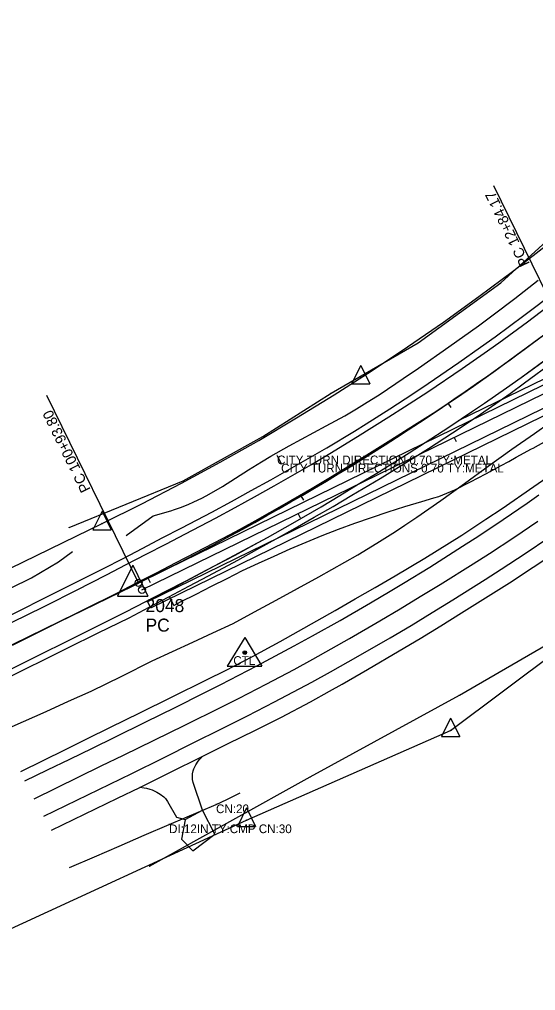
# Model space of a CAD drawing. Extents: x 1674300 to 1677920, y 225056 to 231852.
# Drawn here: x 1676496 to 1676793, y 227452 to 228011 of the extents above; entities that cross this region are included whole.
import ezdxf

# ---------------------------------------------------------------- set-up
doc = ezdxf.new("R2010")
doc.units = 0
for name, color, linetype in [('R_Horz Alg', 7, 'Continuous'), ('R_Horz Alg Annot', 7, 'Continuous'), ('R_Proposed Const Limits_Fill', 7, 'Continuous'), ('R_Proposed Road_Lane', 7, 'Continuous'), ('R_Proposed Road_Shoulder', 7, 'Continuous'), ('S_CAL_CORNER', 7, 'Continuous'), ('S_CAL_CORNER_ANNOT', 7, 'Continuous'), ('S_DITCHLINE', 7, 'Continuous'), ('S_DRG_PT_SYM', 7, 'Continuous'), ('S_EDGE_BITUMINOUS', 7, 'Continuous'), ('S_EDGE_PAVEMENT', 7, 'Continuous'), ('S_EXIST_ROW', 7, 'Continuous'), ('S_EXISTING_ALIGNMENT', 7, 'Continuous'), ('S_FIBER_OPTIC_CABLE', 7, 'Continuous'), ('S_GRAVEL_ROAD', 7, 'Continuous'), ('S_MSC_PT_SYM', 7, 'Continuous'), ('S_PAVEMENT_CROWN', 7, 'Continuous'), ('S_PRIMARY_CTL', 7, 'Continuous'), ('S_SHOULDER', 7, 'Continuous'), ('S_SIDE_DRAIN', 7, 'Continuous'), ('S_SIDE_DRAIN_ANNOT', 7, 'Continuous'), ('S_SIGN', 7, 'Continuous'), ('S_SIGN_ANNOT', 7, 'Continuous'), ('S_UTL_PT_SYM', 7, 'Continuous')]:
    doc.layers.add(name, color=color, linetype=linetype)

msp = doc.modelspace()

# ---------------------------------------------------------------- linework, layer by layer
at = {"layer": 'R_Horz Alg'}
for p, q in [((1676566.75, 227682.84), (1676822.03, 227807.69)), ((1676115.61, 227467.2), (1676564.78, 227686.88))]:
    msp.add_line(p, q, dxfattribs=at)
msp.add_arc((1675928.16, 228988.54), 1449, 296.0624, 0.80558, dxfattribs=at)
at = {"layer": 'R_Horz Alg Annot'}
msp.add_line((1676564.78, 227686.88), (1677389.93, 228090.45), dxfattribs=at)
for points in [[(1676822.03, 227807.69), (1676769.3, 227915.48)], [(1676564.78, 227686.88), (1676512.05, 227794.68)], [(1676744.64, 227787.84), (1676742.95, 227790.32)], [(1676747.73, 227768.01), (1676746.42, 227770.71)], [(1676659.89, 227734.4), (1676658.38, 227736.99)], [(1676657.9, 227724.08), (1676656.58, 227726.77)], [(1676571.67, 227686.93), (1676570.34, 227689.61)]]:
    msp.add_lwpolyline(points, dxfattribs=at)
for centre in [(1676564.78, 227686.88), (1676566.75, 227682.84)]:
    msp.add_circle(centre, 2, dxfattribs=at)
at = {"layer": 'R_Proposed Const Limits_Fill'}
msp.add_line((1676585.15, 227673.94), (1676582.55, 227679.05), dxfattribs=at)
msp.add_lwpolyline([(1676585.15, 227673.94), (1676588.94, 227675.93), (1676597.88, 227680.41), (1676606.76, 227685.02), (1676615.73, 227689.44), (1676624.67, 227693.92), (1676633.73, 227698.17), (1676642.85, 227702.29), (1676651.99, 227706.38), (1676661.2, 227710.33), (1676670.5, 227714.1), (1676679.82, 227717.84), (1676689.32, 227721.21), (1676698.84, 227724.53), (1676708.42, 227727.76), (1676718.1, 227730.78), (1676727.79, 227733.78), (1676734.61, 227735.81), (1676737.54, 227736.67), (1676746.79, 227740.54), (1676755.71, 227745.06), (1676764.59, 227749.65), (1676773.38, 227754.43), (1676777.77, 227756.83), (1676782.16, 227759.23), (1676790.94, 227764.02), (1676791.82, 227764.49), (1676799.7, 227768.86)], dxfattribs=at)
at = {"layer": 'R_Proposed Road_Lane'}
for p, q in [((1676748.93, 227780.28), (1676818.73, 227814.42)), ((1676570.05, 227676.1), (1676825.32, 227800.95)), ((1676570.05, 227676.1), (1676638.9, 227713))]:
    msp.add_line(p, q, dxfattribs=at)
msp.add_lwpolyline([(1676602.96, 227693.74), (1676603.67, 227694.1), (1676620.43, 227702.92), (1676631.53, 227708.93), (1676638.9, 227713), (1676653.56, 227721.26), (1676669.8, 227730.7), (1676680.55, 227737.1), (1676691.25, 227743.62), (1676701.94, 227750.13), (1676720.46, 227761.74), (1676729.67, 227767.63), (1676743.4, 227776.59), (1676757.03, 227785.7), (1676763.8, 227790.32), (1676776.54, 227799.18), (1676784.98, 227805.17), (1676798.91, 227815.26)], dxfattribs=at)
at = {"layer": 'R_Proposed Road_Shoulder'}
for q in [(1676827.08, 227797.35), (1676569.81, 227676.59)]:
    msp.add_line((1676571.81, 227672.51), q, dxfattribs=at)
at = {"layer": 'S_CAL_CORNER'}
for p, q in [((1676561.42, 227697.02), (1676552.61, 227679.29)), ((1676561.42, 227697.02), (1676552.61, 227679.29)), ((1676561.42, 227697.02), (1676552.61, 227679.29)), ((1676561.42, 227697.02), (1676552.61, 227679.29)), ((1676561.42, 227697.02), (1676570.14, 227679.29)), ((1676561.42, 227697.02), (1676570.14, 227679.29)), ((1676561.42, 227697.02), (1676570.14, 227679.29)), ((1676561.42, 227697.02), (1676570.14, 227679.29)), ((1676552.61, 227679.29), (1676570.14, 227679.29)), ((1676552.61, 227679.29), (1676570.14, 227679.29)), ((1676552.61, 227679.29), (1676570.14, 227679.29)), ((1676552.61, 227679.29), (1676570.14, 227679.29))]:
    msp.add_line(p, q, dxfattribs=at)
at = {"layer": 'S_DITCHLINE'}
for points in [[(1676557.64, 227714.12), (1676573.09, 227725.4), (1676583.33, 227728.42), (1676585.43, 227729.06), (1676589.57, 227730.51), (1676593.62, 227732.15), (1676596.28, 227733.34), (1676601.53, 227735.92), (1676605.4, 227738), (1676613.02, 227742.46), (1676628.03, 227751.95), (1676635.56, 227756.66), (1676640.82, 227759.78), (1676651.43, 227765.74), (1676672.81, 227777.22), (1676683.4, 227783.11), (1676690.27, 227787.16), (1676694.8, 227789.93), (1676703.79, 227795.62), (1676717.1, 227804.49), (1676725.88, 227810.55), (1676743.33, 227822.85), (1676760.37, 227834.97), (1676768.81, 227841.12), (1676781.31, 227850.55), (1676794.72, 227861.22)], [(1676485.5, 227601.25), (1676498.51, 227607.06), (1676511.51, 227612.87), (1676524.51, 227618.68), (1676537.51, 227624.49), (1676555.07, 227633.23), (1676572.63, 227641.96), (1676584.27, 227647.35), (1676595.92, 227652.74), (1676607.56, 227658.13), (1676619.21, 227663.52), (1676631.55, 227670.24), (1676643.88, 227676.95), (1676656.22, 227683.66), (1676668.56, 227690.37), (1676683.49, 227698.72), (1676690.87, 227703.03), (1676701.83, 227709.66), (1676712.65, 227716.51), (1676718, 227720.02), (1676724.96, 227724.71), (1676738.72, 227734.32), (1676752.33, 227744.15), (1676765.94, 227753.99), (1676779.59, 227763.79), (1676792.57, 227772.92), (1676809.85, 227785.11)], [(1676454.95, 227666.05), (1676466.98, 227671.97), (1676479.02, 227677.89), (1676491.05, 227683.81), (1676503.09, 227689.73), (1676518.65, 227699.02), (1676526.82, 227704.87)], [(1676609.37, 227559.28), (1676615.59, 227562.13), (1676623.22, 227566.02)], [(1676525.02, 227522.93), (1676539.36, 227529.14), (1676553.7, 227535.35), (1676568.05, 227541.57), (1676582.39, 227547.78)]]:
    msp.add_lwpolyline(points, dxfattribs=at)
at = {"layer": 'S_DRG_PT_SYM'}
for points in [[(1676609.36, 227559.29), (1676609.36, 227559.34), (1676609.36, 227559.29), (1676609.31, 227559.29), (1676609.36, 227559.29), (1676609.36, 227559.24), (1676609.36, 227559.29), (1676609.41, 227559.29)], [(1676582.33, 227547.77), (1676582.33, 227547.82), (1676582.33, 227547.77), (1676582.28, 227547.77), (1676582.33, 227547.77), (1676582.33, 227547.72), (1676582.33, 227547.77), (1676582.38, 227547.77)]]:
    msp.add_lwpolyline(points, dxfattribs=at)
at = {"layer": 'S_EDGE_BITUMINOUS'}
msp.add_lwpolyline([(1676565.47, 227569.19), (1676568.08, 227568.88), (1676569.36, 227568.62), (1676571.23, 227568.11), (1676572.62, 227567.63), (1676575.32, 227566.41), (1676577.23, 227565.29), (1676579.37, 227563.67), (1676580.32, 227562.72), (1676581.5, 227561.06), (1676586.68, 227551.9), (1676591.69, 227550.55), (1676601.59, 227555.91), (1676596.21, 227571.95), (1676595.83, 227573.59), (1676595.74, 227574.69), (1676595.89, 227576.87), (1676596.28, 227578.65), (1676596.66, 227579.8), (1676597.65, 227582.02), (1676599, 227584.13), (1676599.79, 227585.11), (1676601.13, 227586.51)], dxfattribs=at)
at = {"layer": 'S_EDGE_PAVEMENT'}
for points in [[(1676487.21, 227661.87), (1676499.45, 227667.86), (1676511.68, 227673.86), (1676528.99, 227682.71), (1676546.31, 227691.55), (1676557.7, 227697.44), (1676569.08, 227703.32), (1676580.47, 227709.21), (1676591.86, 227715.09), (1676608.97, 227724.09), (1676620.31, 227730.21), (1676631.57, 227736.48), (1676642.83, 227742.74), (1676664.28, 227755.12), (1676674.93, 227761.44), (1676690.82, 227771.09), (1676708.87, 227782.39), (1676717.84, 227788.15), (1676731.2, 227796.91), (1676751.05, 227810.35), (1676763.67, 227819.17), (1676772.03, 227825.14), (1676788.62, 227837.24), (1676807.31, 227851.32)], [(1676484.98, 227634.06), (1676497.37, 227640.22), (1676509.76, 227646.38), (1676522.14, 227652.55), (1676539.8, 227661.38), (1676557.45, 227670.2), (1676569.01, 227676.18), (1676580.56, 227682.15), (1676592.12, 227688.13), (1676603.67, 227694.1), (1676620.43, 227702.92), (1676631.53, 227708.93), (1676638.9, 227713), (1676653.56, 227721.26), (1676669.8, 227730.7), (1676680.55, 227737.1), (1676691.25, 227743.62), (1676701.94, 227750.13), (1676720.46, 227761.74), (1676729.67, 227767.63), (1676743.4, 227776.59), (1676757.03, 227785.7), (1676763.8, 227790.32), (1676776.54, 227799.18), (1676784.98, 227805.17), (1676801.74, 227817.32)], [(1676499.39, 227572.82), (1676512.32, 227579.14), (1676525.26, 227585.45), (1676538.2, 227591.77), (1676551.13, 227598.08), (1676568.66, 227606.72), (1676586.18, 227615.36), (1676601.78, 227623.14), (1676612.15, 227628.41), (1676632.78, 227639.12), (1676654.24, 227650.56), (1676664.91, 227656.39), (1676680.84, 227665.29), (1676698.16, 227675.29), (1676709.63, 227682.09), (1676717.25, 227686.68), (1676732.39, 227696.01), (1676751.22, 227707.95), (1676760.57, 227714.03), (1676774.51, 227723.28), (1676788.32, 227732.7), (1676795.19, 227737.48)], [(1676510.22, 227552.53), (1676522.87, 227558.68), (1676535.53, 227564.83), (1676548.18, 227570.98), (1676560.83, 227577.13), (1676578.71, 227586.01), (1676596.58, 227594.89), (1676612.06, 227602.64), (1676627.54, 227610.4), (1676642.93, 227618.31), (1676664.53, 227629.77), (1676675.26, 227635.64), (1676691.25, 227644.62), (1676709.54, 227655.21), (1676721.65, 227662.42), (1676733.68, 227669.77), (1676745.7, 227677.12), (1676764.28, 227688.81), (1676773.52, 227694.75), (1676787.29, 227703.77), (1676800.96, 227712.96)]]:
    msp.add_lwpolyline(points, dxfattribs=at)
at = {"layer": 'S_EXIST_ROW'}
for p, q in [((1676692.64, 227812.02), (1676687.35, 227801.39)), ((1676692.64, 227812.02), (1676697.88, 227801.39)), ((1676687.35, 227801.39), (1676697.88, 227801.39)), ((1676692.62, 227804.93), (1676692.62, 227804.93)), ((1676543.81, 227728.11), (1676538.52, 227717.47)), ((1676543.81, 227728.11), (1676549.04, 227717.47)), ((1676060.31, 227485.79), (1676543.79, 227721.01)), ((1676538.52, 227717.47), (1676549.04, 227717.47)), ((1676543.79, 227721.01), (1676543.79, 227721.01)), ((1676744.37, 227601.87), (1676877.29, 227701.73)), ((1676744.39, 227608.96), (1676739.1, 227598.33)), ((1676744.39, 227608.96), (1676749.62, 227598.33)), ((1676626.91, 227550.16), (1676744.37, 227601.87)), ((1676744.37, 227601.87), (1676744.37, 227601.87)), ((1676739.1, 227598.33), (1676749.62, 227598.33)), ((1676626.93, 227557.25), (1676621.64, 227546.62)), ((1676626.93, 227557.25), (1676632.16, 227546.62)), ((1676413.97, 227452.12), (1676626.91, 227550.16)), ((1676626.91, 227550.16), (1676626.91, 227550.16)), ((1676621.64, 227546.62), (1676632.16, 227546.62))]:
    msp.add_line(p, q, dxfattribs=at)
for centre, radius in [((1676692.62, 227804.93), 0.18), ((1676692.62, 227804.93), 0.09), ((1676543.79, 227721.01), 0.18), ((1676543.79, 227721.01), 0.09), ((1676744.37, 227601.87), 0.18), ((1676744.37, 227601.87), 0.09), ((1676626.91, 227550.16), 0.18), ((1676626.91, 227550.16), 0.09)]:
    msp.add_circle(centre, radius, dxfattribs=at)
msp.add_arc((1675926.71, 228989.39), 1410.53, 295.94359, 0.85682, dxfattribs=at)
at = {"layer": 'S_EXISTING_ALIGNMENT'}
msp.add_line((1676112.44, 227466.67), (1676561.29, 227685.05), dxfattribs=at)
msp.add_arc((1675926.71, 228989.39), 1450.53, 295.94359, 315.98862, dxfattribs=at)
at = {"layer": 'S_FIBER_OPTIC_CABLE'}
for p, q in [((1676773.26, 227859.62), (1676816.44, 227899.08)), ((1676725.71, 227825.01), (1676773.26, 227859.62)), ((1676675.62, 227796.16), (1676725.71, 227825.01)), ((1676636.29, 227771.17), (1676675.62, 227796.16)), ((1676590.51, 227745.62), (1676636.29, 227771.17)), ((1676524.86, 227718.7), (1676590.51, 227745.62)), ((1676749.48, 227622.29), (1676821.12, 227663.91)), ((1676663.58, 227575.17), (1676749.48, 227622.29)), ((1676571.02, 227523.73), (1676663.58, 227575.17))]:
    msp.add_line(p, q, dxfattribs=at)
at = {"layer": 'S_GRAVEL_ROAD'}
msp.add_lwpolyline([(1676591.68, 227550.52), (1676589.46, 227539.26), (1676596.1, 227532.59), (1676608.73, 227542.23), (1676601.59, 227555.91)], dxfattribs=at)
at = {"layer": 'S_MSC_PT_SYM'}
for points in [[(1676644.47, 227760.17), (1676644.47, 227760.22), (1676644.47, 227760.17), (1676644.42, 227760.17), (1676644.47, 227760.17), (1676644.47, 227760.12), (1676644.47, 227760.17), (1676644.52, 227760.17)], [(1676646.79, 227755.44), (1676646.79, 227755.49), (1676646.79, 227755.44), (1676646.74, 227755.44), (1676646.79, 227755.44), (1676646.79, 227755.39), (1676646.79, 227755.44), (1676646.84, 227755.44)]]:
    msp.add_lwpolyline(points, dxfattribs=at)
at = {"layer": 'S_PAVEMENT_CROWN'}
for points in [[(1676492.18, 227651.02), (1676504.43, 227657.16), (1676516.69, 227663.29), (1676534.44, 227672.12), (1676552.19, 227680.94), (1676563.62, 227686.84), (1676575.04, 227692.73), (1676586.46, 227698.63), (1676597.89, 227704.52), (1676613.1, 227712.47), (1676620.67, 227716.52), (1676631.97, 227722.67), (1676648.78, 227732.15), (1676664.65, 227741.49), (1676675.16, 227747.83), (1676696.09, 227760.67), (1676709.88, 227769.24), (1676723.67, 227777.8), (1676737.33, 227786.55), (1676750.85, 227795.53), (1676757.53, 227800.12), (1676770.18, 227809.13), (1676778.53, 227815.24), (1676795.14, 227827.6)], [(1676504.71, 227562.62), (1676517.55, 227568.9), (1676530.38, 227575.19), (1676543.22, 227581.48), (1676556.06, 227587.76), (1676573.76, 227596.39), (1676591.46, 227605.02), (1676612.34, 227615.32), (1676622.73, 227620.55), (1676638.25, 227628.53), (1676654.34, 227637.08), (1676665.01, 227642.9), (1676686.19, 227654.8), (1676703.71, 227665), (1676715.33, 227671.91), (1676726.88, 227678.95), (1676738.42, 227685.98), (1676757.29, 227697.82), (1676766.67, 227703.83), (1676780.65, 227712.98), (1676794.49, 227722.33)]]:
    msp.add_lwpolyline(points, dxfattribs=at)
at = {"layer": 'S_PRIMARY_CTL'}
for p, q in [((1676625.89, 227655.43), (1676615.86, 227638.92)), ((1676625.89, 227655.43), (1676635.71, 227638.92)), ((1676615.86, 227638.92), (1676635.71, 227638.92))]:
    msp.add_line(p, q, dxfattribs=at)
for radius in [1.04, 0.609, 0.344]:
    msp.add_circle((1676625.89, 227646.73), radius, dxfattribs=at)
at = {"layer": 'S_SHOULDER'}
for points in [[(1676485.19, 227665.35), (1676497.26, 227671.4), (1676509.33, 227677.46), (1676526.95, 227686.28), (1676544.58, 227695.11), (1676555.87, 227700.98), (1676567.16, 227706.86), (1676578.45, 227712.73), (1676589.74, 227718.6), (1676606.9, 227727.65), (1676618.29, 227733.77), (1676629.61, 227740.01), (1676640.94, 227746.25), (1676662.45, 227758.48), (1676673.13, 227764.72), (1676689.03, 227774.29), (1676695.82, 227778.48), (1676709.31, 227787.01), (1676722.68, 227795.72), (1676731.53, 227801.63), (1676749.06, 227813.67), (1676761.63, 227822.56), (1676769.95, 227828.57), (1676786.46, 227840.75), (1676805.03, 227854.85)], [(1676486.61, 227630.79), (1676498.99, 227636.94), (1676511.36, 227643.1), (1676523.74, 227649.26), (1676541.58, 227658.04), (1676559.43, 227666.82), (1676570.84, 227672.86), (1676582.26, 227678.89), (1676593.67, 227684.93), (1676605.09, 227690.97), (1676621.82, 227699.95), (1676632.91, 227706.04), (1676643.95, 227712.24), (1676654.99, 227718.43), (1676665.88, 227724.68), (1676676.77, 227730.93), (1676687.6, 227737.28), (1676703.77, 227746.93), (1676722.45, 227758.42), (1676731.71, 227764.27), (1676745.51, 227773.22), (1676759.16, 227782.38), (1676765.92, 227787.04), (1676778.55, 227795.98), (1676786.9, 227802.03), (1676803.5, 227814.28)], [(1676496.96, 227578.32), (1676509.8, 227584.65), (1676522.64, 227590.98), (1676535.48, 227597.3), (1676548.32, 227603.63), (1676565.85, 227612.23), (1676583.38, 227620.83), (1676604.35, 227631.17), (1676614.79, 227636.43), (1676630.34, 227644.5), (1676646.28, 227653.15), (1676656.84, 227659.05), (1676677.87, 227671.01), (1676689.41, 227677.6), (1676700.95, 227684.2), (1676712.44, 227690.88), (1676729.54, 227701.1), (1676736.64, 227705.48), (1676750.74, 227714.42), (1676764.71, 227723.57), (1676773.96, 227729.76), (1676792.33, 227742.34), (1676809.79, 227754.55)], [(1676514.61, 227544.49), (1676527.31, 227550.65), (1676540.01, 227556.81), (1676552.71, 227562.97), (1676565.42, 227569.13), (1676583.22, 227577.95), (1676601.03, 227586.78), (1676616.37, 227594.33), (1676631.71, 227601.87), (1676646.97, 227609.58), (1676663.66, 227618.43), (1676674.69, 227624.51), (1676682.01, 227628.63), (1676696.58, 227636.99), (1676714.73, 227647.66), (1676726.77, 227654.88), (1676738.73, 227662.21), (1676750.7, 227669.55), (1676769.11, 227681.11), (1676778.26, 227686.98), (1676791.9, 227695.91), (1676805.42, 227705.02)]]:
    msp.add_lwpolyline(points, dxfattribs=at)
at = {"layer": 'S_SIDE_DRAIN'}
msp.add_line((1676582.33, 227547.77), (1676609.36, 227559.29), dxfattribs=at)
at = {"layer": 'S_SIGN'}
msp.add_line((1676644.47, 227760.17), (1676646.79, 227755.44), dxfattribs=at)
at = {"layer": 'S_UTL_PT_SYM'}
for points in [[(1676773.26, 227859.62), (1676773.26, 227859.67), (1676773.26, 227859.62), (1676773.21, 227859.62), (1676773.26, 227859.62), (1676773.26, 227859.57), (1676773.26, 227859.62), (1676773.31, 227859.62)], [(1676725.71, 227825.01), (1676725.71, 227825.06), (1676725.71, 227825.01), (1676725.66, 227825.01), (1676725.71, 227825.01), (1676725.71, 227824.96), (1676725.71, 227825.01), (1676725.76, 227825.01)], [(1676675.62, 227796.16), (1676675.62, 227796.21), (1676675.62, 227796.16), (1676675.57, 227796.16), (1676675.62, 227796.16), (1676675.62, 227796.11), (1676675.62, 227796.16), (1676675.67, 227796.16)], [(1676636.29, 227771.17), (1676636.29, 227771.22), (1676636.29, 227771.17), (1676636.24, 227771.17), (1676636.29, 227771.17), (1676636.29, 227771.12), (1676636.29, 227771.17), (1676636.34, 227771.17)], [(1676590.51, 227745.62), (1676590.51, 227745.67), (1676590.51, 227745.62), (1676590.46, 227745.62), (1676590.51, 227745.62), (1676590.51, 227745.57), (1676590.51, 227745.62), (1676590.56, 227745.62)], [(1676524.86, 227718.7), (1676524.86, 227718.75), (1676524.86, 227718.7), (1676524.81, 227718.7), (1676524.86, 227718.7), (1676524.86, 227718.65), (1676524.86, 227718.7), (1676524.91, 227718.7)], [(1676749.48, 227622.29), (1676749.48, 227622.34), (1676749.48, 227622.29), (1676749.43, 227622.29), (1676749.48, 227622.29), (1676749.48, 227622.24), (1676749.48, 227622.29), (1676749.53, 227622.29)], [(1676663.58, 227575.17), (1676663.58, 227575.22), (1676663.58, 227575.17), (1676663.53, 227575.17), (1676663.58, 227575.17), (1676663.58, 227575.12), (1676663.58, 227575.17), (1676663.63, 227575.17)], [(1676571.02, 227523.73), (1676571.02, 227523.78), (1676571.02, 227523.73), (1676570.97, 227523.73), (1676571.02, 227523.73), (1676571.02, 227523.68), (1676571.02, 227523.73), (1676571.07, 227523.73)]]:
    msp.add_lwpolyline(points, dxfattribs=at)

# ---------------------------------------------------------------- texts
at = {"layer": 'R_Horz Alg Annot'}
for s, p in [('PC 12+84.17', (1676790.07, 227870.74)), ('PC 100+93.80', (1676537.33, 227740.72))]:
    msp.add_text(s, height=6, rotation=116.0624, dxfattribs=at).set_placement(p)
at = {"layer": 'S_CAL_CORNER_ANNOT'}
for s, p in [('2048', (1676568.79, 227670.05)), ('2048', (1676568.79, 227670.05)), ('2048', (1676568.79, 227670.05)), ('2048', (1676568.79, 227670.05)), ('PC', (1676568.79, 227658.8)), ('PC', (1676568.79, 227658.8)), ('PC', (1676568.79, 227658.8)), ('PC', (1676568.79, 227658.8))]:
    msp.add_text(s, height=7.5, rotation=360, dxfattribs=at).set_placement(p)
at = {"layer": 'S_PRIMARY_CTL'}
msp.add_text('CTL', height=5, rotation=360, dxfattribs=at).set_placement((1676619.3, 227639.65))
at = {"layer": 'S_SIDE_DRAIN_ANNOT'}
for s, p in [('CN:20', (1676609.36, 227554.29)), ('DI:12IN TY:CMP CN:30', (1676582.33, 227542.77))]:
    msp.add_text(s, height=5, rotation=360, dxfattribs=at).set_placement(p)
at = {"layer": 'S_SIGN_ANNOT'}
for s, p in [('CITY TURN DIRECTION 0.70 TY:METAL', (1676644.47, 227755.17)), ('CITY TURN DIRECTIONS 0.70 TY:METAL', (1676646.79, 227750.44))]:
    msp.add_text(s, height=5, rotation=360, dxfattribs=at).set_placement(p)

doc.saveas('drawing.dxf')
